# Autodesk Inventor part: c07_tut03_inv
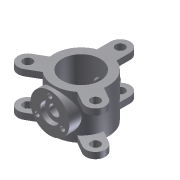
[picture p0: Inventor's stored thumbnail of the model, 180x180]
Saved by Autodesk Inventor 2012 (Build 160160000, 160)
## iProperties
Created: 2010-03
Part Number: c07_tut03_inv
Document SubType Name: Modeling
Designer: CADSoft
Density: 1 g/cm^3
Material: Default
Author: CADSoft
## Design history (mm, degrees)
sketch "Sketch1"
  geometry: C1 r 97 at (0, 0); C2 r 140 at (0, 0); 1 further point
  constraints: 2 centre point, 2 coincident
  dimensions: "d0" = 194 diameter of C1; "d1" = 280 diameter of C2
extrude "Extrusion1" new body sketch "Sketch1" stored distance "d2" = 225; taper "d3" = 0 deg
workplane "Work Plane1"
sketch "Sketch2"
  geometry: C1 r 100 at (0, 0); 1 further point
  constraints: 1 centre point, 1 coincident
  dimensions: "d5" = 200 diameter of C1
extrude "Extrusion2" join sketch "Sketch2" stored distance "d6" = 225; taper "d7" = 0 deg
workplane "Work Plane2"
sketch "Sketch3"
  geometry: C1 r 37.5 at (0, 0); 1 further point
  constraints: 1 centre point, 1 coincident
  dimensions: "d9" = 75 diameter of C1
extrude "Extrusion3" join sketch "Sketch3" stored distance "d10" = 225; taper "d11" = 0 deg
hole "Hole1" diameter "d14" = 56; stored, may be unused: countersink angle "d18" = 90 deg, drill point angle "d20" = 0 deg; dims "d12" = 10, "d13" = 10, "d15" = 6, "d16" = 100, "d17" = 25, "d19" = 310
sketch "Sketch4"
  geometry: C1 r 50 at (0, 0) reference; 1 further point
  constraints: 1 vertical alignment
  dimensions: "d21" = 75 distance of C1.centre point (0, 75)
hole "Hole2" sketch "Sketch4" at (0, 75) diameter "d22" = 24; stored, may be unused: countersink angle "d26" = 90 deg, drill point angle "d28" = 118 deg; dims "d23" = 6, "d24" = 100, "d25" = 25, "d27" = 15
pattern_circular "Circular Pattern1" dims angle "d30" = 360 deg
sketch "Sketch5"
  geometry: L1 (-50, 200)-(-50, 130.767); L2 (50, 200)-(50, 130.767); L3 (0, 0)-(0, 306.095); C1 r 97 at (0, 0) reference; C2 r 23.5 at (0, 200); A1 r 140 centre (0, 0) between (-50, 130.767) and (50, 130.767) reference; A2 r 50 centre (0, 200) between (50, 200) and (-50, 200); A3 r 140 centre (0, 0) between (50, 130.767) and (-50, 130.767)
  constraints: 7 point on circle, 6 end point, 3 centre point, 2 coincident, 2 tangent, 1 other
  dimensions: "d32" = 200 distance of A2.centre C1.centre; "d33" = 50 radius of A2; "d34" = 47 diameter of C2
extrude "Extrusion4" join sketch "Sketch5" distance "d35" = 32; taper "d36" = 0 deg
pattern_circular "Circular Pattern2" dims angle "d38" = 360 deg
mirror "Mirror1"
body "Solid1"
other parameters: "d8" = 325
